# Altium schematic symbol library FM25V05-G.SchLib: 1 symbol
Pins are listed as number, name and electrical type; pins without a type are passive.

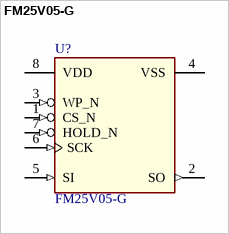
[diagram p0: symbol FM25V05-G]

## FM25V05-G
designator U?
4-Kbit (512 × 8) Serial (SPI) F-RAM; Manufacturer: Infineon Technologies
pins: 1 CS_N (in) "Chip Select", 2 SO (out) "Serial Output", 3 WP_N (in) "Write Protect", 4 VSS (power) "Ground for the device. Must be connected to the ground of the system", 5 SI (in) "Serial Input", 6 SCK (in) "Serial Clock", 7 HOLD_N (in) "The HOLD pin is used when the host CPU must interrupt a memory operation for another  task.", 8 VDD (power) "Power supply input to the device."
